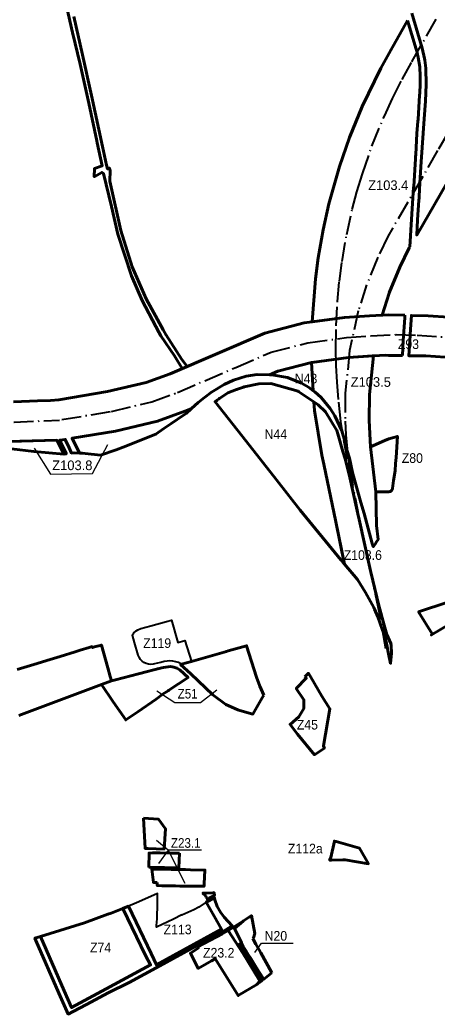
# Model space of a CAD drawing. Extents: x -650277 to -643422, y -1073980 to -1066720.
# Drawn here: x -648765 to -647728, y -1070690 to -1068218 of the extents above; entities that cross this region are included whole.
import ezdxf

# ---------------------------------------------------------------- set-up
doc = ezdxf.new("R2010")
doc.units = 0
doc.header["$LTSCALE"] = 9.6
doc.header["$PDMODE"] = 32
doc.header["$PDSIZE"] = 4.8
doc.linetypes.add('DOT_DASHED', pattern=[7.7, 5, -1.2, 0.3, -1.2])
for name, color, linetype, lineweight in [('1', 7, 'Continuous', 60), ('15', 7, 'Continuous', 60), ('2', 7, 'Continuous', 40), ('3', 7, 'Continuous', 60), ('35', 7, 'Continuous', 60), ('36', 7, 'Continuous', 60), ('40', 7, 'Continuous', 60), ('42', 7, 'Continuous', 60), ('59', 7, 'Continuous', 25), ('60', 7, 'Continuous', 60), ('61', 7, 'Continuous', 60), ('62', 7, 'DOT_DASHED', 40), ('63', 7, 'Continuous', 25), ('7', 7, 'Continuous', 60), ('9', 7, 'Continuous', 60)]:
    doc.layers.add(name, color=color, linetype=linetype, lineweight=lineweight)

msp = doc.modelspace()

# ---------------------------------------------------------------- linework, layer by layer
at = {"layer": '1', "lineweight": 40}
msp.add_lwpolyline([(-648339.05, -1069812.45), (-648363.68, -1069819.31), (-648371.21, -1069815.56), (-648378.1, -1069813.29), (-648385.21, -1069811.91), (-648392.45, -1069811.44), (-648399.68, -1069811.88), (-648406.84, -1069813.23), (-648414.657, -1069815.246), (-648415.99, -1069815.59), (-648430.881, -1069818.663), (-648433.97, -1069819.3), (-648439.89, -1069819.97), (-648445.8, -1069819.51), (-648451.53, -1069817.98), (-648456.88, -1069815.39), (-648461.64, -1069811.86), (-648465.67, -1069807.49), (-648468.82, -1069802.44), (-648470.97, -1069796.9), (-648480.267, -1069765.316), (-648485.44, -1069747.39), (-648485.14, -1069746.55), (-648483.274, -1069743.777), (-648481.79, -1069741.57), (-648477.39, -1069737.44), (-648476.022, -1069736.525), (-648472.4, -1069734.1), (-648464.45, -1069730.89), (-648439.8, -1069724.19), (-648401.288, -1069713.154), (-648388.631, -1069709.738), (-648372.639, -1069765.241), (-648355.015, -1069760.287)], close=True, dxfattribs=at)
at = {"layer": '1'}
msp.add_lwpolyline([(-648458.28, -1070202.26), (-648454.038, -1070277.767), (-648446.18, -1070278.15), (-648406.8, -1070279.32), (-648403.04, -1070229.15), (-648420.7, -1070204.96)], close=True, dxfattribs=at)
for points in [[(-648368.25, -1070289.71), (-648372.1, -1070289.59), (-648380.97, -1070289.44), (-648392.94, -1070289.25), (-648416.93, -1070288.85), (-648420.39, -1070288.79), (-648428.98, -1070288.92), (-648435.93, -1070288.95), (-648444.15, -1070289.16), (-648444.85, -1070324.47)], [(-648444.85, -1070324.47), (-648444.85, -1070324.47), (-648430.02, -1070324.76), (-648418.1, -1070325), (-648406.09, -1070325.23), (-648394.08, -1070325.47), (-648382.06, -1070325.7), (-648370.07, -1070325.94), (-648368.25, -1070289.71)], [(-648307.13, -1070365.57), (-648305.47, -1070331.23), (-648341.46, -1070330.48), (-648353.32, -1070330.23), (-648365.35, -1070329.98), (-648389.43, -1070329.58), (-648401.41, -1070329.39), (-648413.45, -1070329.19), (-648425.43, -1070329), (-648437.65, -1070328.8), (-648433.46, -1070361.94), (-648424.31, -1070362.21)], [(-648424.31, -1070362.21), (-648424.05, -1070370), (-648412.75, -1070370.28), (-648401.35, -1070370.5), (-648390.06, -1070370.72), (-648378.73, -1070370.94), (-648367.67, -1070371.16), (-648355.67, -1070371.28), (-648343.67, -1070371.41), (-648331.67, -1070371.53), (-648319.67, -1070371.65), (-648307.67, -1070371.78), (-648307.13, -1070365.57)]]:
    msp.add_lwpolyline(points, dxfattribs=at)
at = {"layer": '15'}
for points in [[(-648349.419, -1069079.223), (-648362.06, -1069084.664), (-648381.44, -1069052.48), (-648415.29, -1069003.16), (-648419.78, -1068994.25), (-648427.21, -1068980.13), (-648461.22, -1068915.44), (-648488.09, -1068854.16), (-648521.92, -1068750.34), (-648537.29, -1068681.95), (-648557.4, -1068599.9), (-648559.44, -1068598.37), (-648561.49, -1068596.84), (-648580.66, -1068607.64), (-648579.97, -1068587.39), (-648560.79, -1068580.12), (-648572.95, -1068522.97), (-648573.96, -1068518.34), (-648594.38, -1068425.02), (-648615.87, -1068327.3), (-648634.84, -1068248.76), (-648655.88, -1068153.63)], [(-648630.99, -1068209.19), (-648610.14, -1068304.32), (-648587.39, -1068405.82), (-648559.91, -1068532.62), (-648549.84, -1068578.65), (-648547.25, -1068588.14), (-648542.93, -1068586.13), (-648541.74, -1068589.27)], [(-648541.74, -1068589.27), (-648541.25, -1068592.3), (-648541.89, -1068618.64), (-648514.35, -1068741.53), (-648486.25, -1068831.83), (-648451.76, -1068910.91), (-648409.15, -1068988.44), (-648402.76, -1069000.2), (-648363.11, -1069061.72), (-648349.419, -1069079.223)], [(-648213.87, -1070524.8), (-648221.359, -1070516.349), (-648215.48, -1070512.59), (-648214.34, -1070511.86), (-648231.53, -1070476.99), (-648210.48, -1070458.42), (-648247.67, -1070481.57), (-648211, -1070538)], [(-648176.54, -1070616.09), (-648169.28, -1070610.49), (-648163.8, -1070606.27), (-648213.87, -1070524.8)], [(-648211, -1070538), (-648168.575, -1070607.847), (-648176.54, -1070616.09)]]:
    msp.add_lwpolyline(points, dxfattribs=at)
for points in [[(-648550.72, -1070626.869), (-648636.757, -1070673.431), (-648655.178, -1070631.294), (-648714.161, -1070496.376), (-648728.255, -1070500.709), (-648725.835, -1070506.221), (-648668.207, -1070637.453), (-648645.331, -1070689.546), (-648632.652, -1070682.82), (-648599.66, -1070665.32), (-648545.76, -1070636.22), (-648494.04, -1070610.73), (-648417.855, -1070569.57), (-648325.21, -1070518.84), (-648264.56, -1070486.34), (-648260.57, -1070484.2), (-648237.475, -1070470.361), (-648257.96, -1070448.17), (-648266.416, -1070436.404), (-648274.808, -1070421.647), (-648280.974, -1070405.11), (-648281.388, -1070400.523), (-648302.01, -1070411.05), (-648282.01, -1070446.35), (-648263.859, -1070478.393), (-648425.835, -1070567.021), (-648439.409, -1070538.729), (-648495.666, -1070421.476), (-648509.227, -1070426.957), (-648452.97, -1070544.21), (-648440.531, -1070567.236)], [(-648303.705, -1070395.035), (-648302.028, -1070398.436), (-648299.32, -1070403.93), (-648295.18, -1070401.23), (-648281.907, -1070394.762), (-648282.582, -1070387.276), (-648284.37, -1070387.85), (-648310.275, -1070388.476)]]:
    msp.add_lwpolyline(points, close=True, dxfattribs=at)
msp.add_point((-648213.87, -1070524.8), dxfattribs=at)
at = {"layer": '2'}
msp.add_lwpolyline([(-648495.666, -1070421.476), (-648439.409, -1070538.729), (-648425.835, -1070567.021), (-648267.801, -1070480.55), (-648263.859, -1070478.393), (-648282.01, -1070446.35), (-648302.01, -1070411.05), (-648320.24, -1070423.64), (-648332.97, -1070430.18), (-648362.79, -1070443.63), (-648363.1, -1070443.1), (-648383.61, -1070453.86), (-648426.05, -1070473.34), (-648425.71, -1070468.87), (-648424.47, -1070452.7), (-648423.56, -1070413.35), (-648423.005, -1070389.357), (-648469.77, -1070410.47), (-648481.18, -1070415.62)], close=True, dxfattribs=at)
at = {"layer": '3'}
msp.add_lwpolyline([(-648767.83, -1069946.87), (-648562.242, -1069870.301), (-648537.86, -1069861.22), (-648541.06, -1069849.78), (-648546.97, -1069828.68), (-648562.87, -1069771.85), (-648579.63, -1069776.66), (-648584.65, -1069778.1), (-648586.09, -1069775.75), (-648593.59, -1069778.06), (-648615.88, -1069784.93), (-648627.99, -1069788.67), (-648665.05, -1069799.99), (-648698.31, -1069810.16), (-648722.24, -1069817.54), (-648772.48, -1069832.83)], dxfattribs=at)
for points in [[(-648159.1, -1069896.39), (-648169.15, -1069873.81), (-648176.78, -1069851.74), (-648201.83, -1069773.86), (-648247.27, -1069786.64), (-648251.94, -1069787.95), (-648339.05, -1069812.45), (-648363.68, -1069819.31), (-648365.81, -1069819.9), (-648340.38, -1069843.78), (-648285.62, -1069895.71), (-648253.13, -1069919.7), (-648223.99, -1069932.96), (-648218.245, -1069934.595), (-648186.268, -1069943.697), (-648160.04, -1069897.73)], [(-648470.79, -1069843.51), (-648528.11, -1069858.73), (-648537.86, -1069861.22), (-648562.242, -1069870.301), (-648533.79, -1069913.49), (-648502.048, -1069957.969), (-648472.6, -1069937.81), (-648426.82, -1069906.88), (-648409.44, -1069893.25), (-648396.87, -1069885.43), (-648395.03, -1069884.22), (-648347.06, -1069853), (-648367.64, -1069833.35), (-648374.89, -1069829.22), (-648382.8, -1069826.55), (-648391.08, -1069825.45), (-648408.45, -1069827.83), (-648412.74, -1069828.72), (-648422.75, -1069830.78), (-648435.53, -1069834.44), (-648447.98, -1069837.44)], [(-648057.11, -1069851.12), (-648053.61, -1069854.64), (-648078.54, -1069880.01), (-648059.32, -1069908.27), (-648059.5, -1069929.52), (-648071.58, -1069950.39), (-648093.67, -1069969.42), (-648074.96, -1069993.46), (-648032.85, -1070044.73), (-648008.18, -1070028.25), (-648010.44, -1070023.66), (-648010.94, -1070022.65), (-647994.71, -1069930.53), (-648015.11, -1069898.98), (-648032.94, -1069867.46), (-648048.08, -1069841.95)]]:
    msp.add_lwpolyline(points, close=True, dxfattribs=at)
at = {"layer": '35'}
msp.add_lwpolyline([(-647740.74, -1069744.24), (-647742.36, -1069746.93), (-647674.901, -1069706.701), (-647560.36, -1069638.39), (-647570.37, -1069621.18), (-647701.61, -1069665.279), (-647774.11, -1069689.64)], close=True, dxfattribs=at)
at = {"layer": '36'}
for points in [[(-647962.82, -1070305.9), (-647956.36, -1070305.77), (-647898.82, -1070315.51), (-647921.51, -1070276.76), (-647979.24, -1070260.71), (-647983.6, -1070259.5), (-647992.71, -1070300.01), (-647995.46, -1070306.55), (-647991.12, -1070306.46)], [(-648636.757, -1070673.431), (-648550.72, -1070626.869), (-648440.531, -1070567.236), (-648452.97, -1070544.21), (-648509.227, -1070426.957), (-648526.28, -1070433.85), (-648538.611, -1070438.388), (-648546.377, -1070441.246), (-648604.92, -1070462.79), (-648714.161, -1070496.376), (-648655.178, -1070631.294)], [(-648636.757, -1070673.431), (-648550.72, -1070626.869), (-648440.531, -1070567.236), (-648452.97, -1070544.21), (-648509.227, -1070426.957), (-648526.28, -1070433.85), (-648538.611, -1070438.388), (-648546.377, -1070441.246), (-648604.92, -1070462.79), (-648714.161, -1070496.376), (-648655.178, -1070631.294)]]:
    msp.add_lwpolyline(points, close=True, dxfattribs=at)
at = {"layer": '40'}
msp.add_line((-648214.34, -1070511.86), (-648215.48, -1070512.59), dxfattribs=at)
for points in [[(-648186.441, -1070501.65), (-648186.088, -1070501.313), (-648184.791, -1070500.073), (-648181.386, -1070488.724), (-648189.93, -1070444.71), (-648194.56, -1070447.8), (-648194.56, -1070447.799), (-648209.82, -1070457.98), (-648210.48, -1070458.42), (-648231.53, -1070476.99), (-648214.34, -1070511.86)], [(-648215.48, -1070512.59), (-648210.19, -1070521.07), (-648203.83, -1070531.25), (-648197.59, -1070541.27), (-648190.71, -1070552.3), (-648182.98, -1070564.68), (-648171.02, -1070583.86), (-648159.23, -1070602.75), (-648138.93, -1070587.1)], [(-648166.63, -1070537.28), (-648170.72, -1070529.92), (-648172.96, -1070525.9), (-648178.7, -1070515.58), (-648184.54, -1070505.07), (-648186.441, -1070501.65)], [(-648138.93, -1070587.1), (-648140.05, -1070585.09), (-648166.63, -1070537.28)]]:
    msp.add_lwpolyline(points, dxfattribs=at)
at = {"layer": '42'}
msp.add_lwpolyline([(-648100.37, -1069107.1), (-648065.16, -1069121.12), (-648048.06, -1069130.81), (-648036.291, -1069139.458), (-648040.705, -1069069.547), (-648124.327, -1069091.181), (-648144.867, -1069099.987), (-648139.27, -1069100.05), (-648100.37, -1069107.1)], close=True, dxfattribs=at)
at = {"layer": '60'}
for points in [[(-647864.531, -1068951.823), (-647895.901, -1068953.392), (-647958.168, -1068957.73), (-648038.596, -1068968.281), (-648038.759, -1068968.54)], [(-647808.28, -1068952.066), (-647850.043, -1068951.098), (-647864.531, -1068951.823)], [(-647814.401, -1069052.246), (-647812.34, -1069014.54), (-647808.67, -1068958.06), (-647808.28, -1068952.066)], [(-647699.561, -1068956.635), (-647749.978, -1068953.416), (-647792.01, -1068952.442), (-647794.21, -1068986.12), (-647796.13, -1069015.57), (-647798.631, -1069052.508), (-647756.441, -1069053.207), (-647708.401, -1069056.275)], [(-648038.759, -1068968.54), (-648038.746, -1068968.301), (-648058.764, -1068970.927), (-648156.739, -1068996.273), (-648392.002, -1069097.554), (-648451.865, -1069119.456), (-648547.243, -1069141.81), (-648668.959, -1069161.838), (-648688.912, -1069163.603), (-648721.315, -1069164.952), (-648781.015, -1069167.44)], [(-648040.705, -1069069.547), (-648039.666, -1069069.279), (-647948.18, -1069057.276), (-647886.615, -1069053.052), (-647856.541, -1069051.548), (-647848.615, -1069051.679), (-647842.888, -1069051.774), (-647814.401, -1069052.246)], [(-648918.889, -1069268.875), (-648673.267, -1069262.895), (-648656.242, -1069297.116), (-648650.06, -1069296.39), (-648650.58, -1069295.34), (-648658.18, -1069280.27), (-648666.827, -1069262.738), (-648665.007, -1069262.694), (-648665.007, -1069262.694), (-648652.716, -1069260.657), (-648642.74, -1069281.93), (-648636.85, -1069294.49), (-648630.82, -1069293.63), (-648617.434, -1069294.508), (-648635.818, -1069257.857), (-648527.693, -1069239.938), (-648423.173, -1069215.44), (-648354.978, -1069190.492), (-648338.523, -1069183.389), (-648322.14, -1069168.56), (-648306.83, -1069156.57), (-648289.25, -1069142.79), (-648257.5, -1069124.41), (-648234.22, -1069113.6), (-648202.46, -1069103.3), (-648175.65, -1069099.64), (-648144.866, -1069099.987), (-648124.327, -1069091.181), (-648040.705, -1069069.547)], [(-648526.15, -1069286.21), (-648508.95, -1069280.01), (-648427.08, -1069247.75), (-648407.73, -1069233.88), (-648389.91, -1069221.86), (-648355.81, -1069198.88), (-648351.77, -1069195.88), (-648338.523, -1069183.389), (-648354.978, -1069190.492)], [(-648354.978, -1069190.492), (-648423.173, -1069215.44), (-648527.693, -1069239.938), (-648635.818, -1069257.857)], [(-648635.818, -1069257.857), (-648622.995, -1069283.455), (-648617.434, -1069294.508)], [(-648617.434, -1069294.508), (-648609.425, -1069295.033), (-648603.228, -1069295.53), (-648565.18, -1069299.46), (-648526.15, -1069286.21)]]:
    msp.add_lwpolyline(points, dxfattribs=at)
for points in [[(-648730.66, -1069290.43), (-648656.242, -1069297.116), (-648673.267, -1069262.895), (-648761.189, -1069265.035), (-648918.889, -1069268.875), (-648909.86, -1069270.02), (-648861.49, -1069275.34), (-648785.92, -1069284.2), (-648730.66, -1069290.43)], [(-647860.52, -1069390.72), (-647848.24, -1069390.65), (-647845.25, -1069390.07), (-647843.41, -1069389.23), (-647841.81, -1069387.99), (-647840.42, -1069386.51), (-647839.4, -1069384.73), (-647838.79, -1069382.86), (-647836.2, -1069362.68), (-647832.29, -1069338.58), (-647832.29, -1069338.58), (-647831.19, -1069320.69), (-647830.23, -1069305.38), (-647826.928, -1069253.199), (-647848.17, -1069259.21), (-647858.37, -1069263.03), (-647893.553, -1069279.017), (-647880.326, -1069390.832)]]:
    msp.add_lwpolyline(points, close=True, dxfattribs=at)
msp.add_arc((-648354.978, -1069190.492), 0.000000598, 264.13978, 298.69712, dxfattribs=at)
at = {"layer": '61'}
msp.add_line((-648038.596, -1068968.281), (-647958.168, -1068957.73), dxfattribs=at)
for points in [[(-647791.055, -1068200.507), (-647765.22, -1068287.94), (-647759.412, -1068313.436)], [(-647801.797, -1068219.34), (-647843.6, -1068292.629), (-647868.214, -1068337.803), (-647914.339, -1068432.512), (-647946.187, -1068510.254), (-647971.074, -1068581.98), (-647997.27, -1068674.747), (-648011.775, -1068739.718), (-648023.914, -1068809.332), (-648030.73, -1068861.213), (-648038.596, -1068968.281)], [(-647771.413, -1068334.626), (-647774.94, -1068311.47), (-647779.55, -1068292.23), (-647780.07, -1068290.53), (-647801.797, -1068219.34)], [(-647768.02, -1068570.36), (-647770.94, -1068622.47), (-647772.85, -1068656.41), (-647773.08, -1068660.57), (-647773.4, -1068665.71), (-647776.5, -1068714.8), (-647778.95, -1068752.433), (-647675.054, -1068572.919), (-647535.844, -1068336.279), (-647464.94, -1068215.752)], [(-647759.412, -1068313.436), (-647758.45, -1068317.66), (-647756.09, -1068337.61), (-647754.99, -1068378.21), (-647757.41, -1068419.98), (-647760.22, -1068463.96), (-647768.02, -1068570.36)], [(-647796.173, -1068782.191), (-647791.77, -1068713.23), (-647786.47, -1068634.37), (-647786.32, -1068632.19), (-647781.85, -1068562.97), (-647781.55, -1068558.38), (-647781.13, -1068551.88), (-647778.24, -1068499.95), (-647775.82, -1068469.74), (-647775.52, -1068464.97), (-647771.74, -1068404.5), (-647771.47, -1068400.07), (-647770.12, -1068377.5), (-647769.92, -1068352.1), (-647770.81, -1068340.29), (-647771.05, -1068337.01), (-647771.413, -1068334.626)], [(-647846.989, -1068896.545), (-647820.883, -1068832.117), (-647797.632, -1068784.713), (-647796.173, -1068782.191)], [(-647958.168, -1068957.73), (-647895.901, -1068953.392), (-647864.531, -1068951.823), (-647847.197, -1068897.199), (-647847.034, -1068896.687), (-647846.989, -1068896.545)], [(-647948.18, -1069057.276), (-648039.666, -1069069.279), (-648040.705, -1069069.548), (-648036.291, -1069139.458)], [(-647886.615, -1069053.052), (-647889.927, -1069053.218), (-647948.18, -1069057.276)], [(-647893.553, -1069279.017), (-647896.67, -1069213.573), (-647896.362, -1069149.171), (-647886.615, -1069053.052)], [(-648036.291, -1069139.458), (-648031.92, -1069142.67), (-648016.36, -1069156.54), (-647993.8, -1069184.11)], [(-648005.47, -1069192.09), (-648024.02, -1069174.7), (-648034.421, -1069167.61)], [(-648034.421, -1069167.61), (-648034.421, -1069167.61), (-648033, -1069189), (-648015, -1069300), (-648010.092, -1069322.087), (-647980.331, -1069465.915), (-647958.34, -1069570.699), (-647925.99, -1069608.57), (-647906.16, -1069641.48), (-647885.665, -1069678.788), (-647885.663, -1069678.794), (-647883.51, -1069682.71), (-647875.82, -1069701.85), (-647875.82, -1069701.85), (-647864.19, -1069735.12), (-647858.44, -1069749.43), (-647852.63, -1069775.7), (-647850.66, -1069785.74), (-647849.165, -1069793.367)], [(-647993.8, -1069184.11), (-647982.58, -1069202.33), (-647965.06, -1069238.95), (-647957.56, -1069264.74), (-647953.01, -1069285.73), (-647951.841, -1069289.09)], [(-647962.2, -1069290.88), (-647974.81, -1069246.86), (-647977.29, -1069238.21), (-648005.47, -1069192.09)], [(-647880.326, -1069390.832), (-647880.326, -1069390.832), (-647893.553, -1069279.017)], [(-647852.78, -1069745.71), (-647859.722, -1069722.428), (-647872.87, -1069673.56), (-647892.79, -1069591.06), (-647892.789, -1069591.06), (-647893.75, -1069587.08), (-647922.04, -1069459.71), (-647925.16, -1069445.68), (-647928.41, -1069431.03), (-647945.28, -1069355.1), (-647956.27, -1069311.58), (-647962.2, -1069290.88)], [(-647951.841, -1069289.09), (-647945.63, -1069306.95), (-647938.77, -1069343.17), (-647918.08, -1069417.43), (-647909.67, -1069444.46), (-647889.22, -1069519.32), (-647887.087, -1069527.229), (-647885.782, -1069525.389), (-647882.551, -1069520.835), (-647878.73, -1069515.45)], [(-647878.73, -1069515.45), (-647874.75, -1069509.84), (-647878.93, -1069475.09), (-647880.318, -1069391.297), (-647880.326, -1069390.832)], [(-647841.402, -1069792.351), (-647842.489, -1069773.282), (-647842.622, -1069770.956), (-647843.337, -1069769.013), (-647843.443, -1069768.293), (-647852.78, -1069745.71)], [(-647849.165, -1069793.367), (-647843.74, -1069817.63), (-647841.402, -1069792.351)]]:
    msp.add_lwpolyline(points, dxfattribs=at)
at = {"layer": '62'}
for points in [[(-647128.118, -1067439.088), (-647164.761, -1067539.408), (-647210.113, -1067645.071), (-647251.182, -1067728.502), (-647325.296, -1067860.04), (-647512.903, -1068178.95), (-647726.877, -1068542.68), (-647850.594, -1068756.441), (-647875.691, -1068807.609), (-647903.473, -1068876.174), (-647924.037, -1068940.973), (-647945.559, -1069039.601), (-647956.348, -1069145.994), (-647956.677, -1069214.977), (-647954.925, -1069248.93), (-647950.785, -1069292.731), (-647945.699, -1069329.377), (-647937.748, -1069374.683)], [(-647855.282, -1069780.988), (-647871.488, -1069692.474), (-647887.497, -1069616.134), (-647904.75, -1069533.925), (-647921.593, -1069453.674), (-647951.177, -1069310.704), (-647961.781, -1069251.651), (-647967.108, -1069216.048), (-647973.483, -1069161.422), (-647976.974, -1069118.566), (-647979.115, -1069076.622), (-647979.994, -1069035.633), (-647979.227, -1068978.642), (-647975.845, -1068917.741), (-647971.102, -1068867.969), (-647964.589, -1068818.397), (-647952.909, -1068751.415), (-647938.965, -1068688.958), (-647927.463, -1068645.455), (-647913.969, -1068600.436), (-647890.042, -1068531.477), (-647859.34, -1068456.533), (-647839.124, -1068413.001), (-647815.115, -1068365.753), (-647791.193, -1068321.849), (-647729.261, -1068213.27)], [(-647953.174, -1069007.503), (-647892.914, -1069003.305), (-647829.936, -1069000.155), (-647777.98, -1069001.73), (-647703.981, -1069006.455), (-647634.706, -1069014.33), (-647507.176, -1069026.93), (-647422.156, -1069034.805), (-647341.859, -1069041.105), (-647269.435, -1069044.255), (-647198.585, -1069044.255), (-647126.161, -1069041.105), (-647071.055, -1069037.955), (-646992.775, -1069025.505), (-646951.398, -1069008.03), (-646907.314, -1068982.831), (-646861.655, -1068949.756), (-646819.145, -1068907.232), (-646779.784, -1068863.132), (-646712.083, -1068781.233), (-646669.79, -1068726.705)], [(-648660.841, -1069211.175), (-648537.468, -1069190.874), (-648437.519, -1069167.448), (-648373.49, -1069144.023), (-648228.701, -1069081.527), (-648140.533, -1069043.727), (-648049.215, -1069020.103), (-647953.174, -1069007.503)], [(-649319.032, -1069251.01), (-649228.433, -1069229.954), (-649166.697, -1069221.478), (-649075.909, -1069222.689), (-648779.53, -1069217.422), (-648667.088, -1069212.737)]]:
    msp.add_lwpolyline(points, dxfattribs=at)
at = {"layer": '63'}
for q in [(-648421, -1070315), (-648355.27, -1070364.25)]:
    msp.add_line((-648397, -1070282), q, dxfattribs=at)
for points in [[(-648730, -1069282), (-648689.019, -1069347.095), (-648585, -1069345.095), (-648547, -1069273)], [(-648425, -1069886), (-648380, -1069915), (-648316, -1069915), (-648276, -1069883)], [(-648314, -1070282), (-648397, -1070282), (-648426, -1070258)], [(-648181, -1070536), (-648165, -1070513), (-648086, -1070513)]]:
    msp.add_lwpolyline(points, dxfattribs=at)
at = {"layer": '7'}
msp.add_lwpolyline([(-648247.67, -1070481.57), (-648262.69, -1070489.67), (-648323.59, -1070522.48), (-648322.18, -1070525.44), (-648341.41, -1070538.42), (-648322.16, -1070575.76), (-648289.22, -1070557.15), (-648279.736, -1070551.783), (-648278.89, -1070553.14), (-648222.58, -1070643.48), (-648176.54, -1070616.09), (-648168.575, -1070607.847), (-648211, -1070538)], close=True, dxfattribs=at)
at = {"layer": '9'}
msp.add_lwpolyline([(-648015, -1069300), (-648033, -1069189), (-648034.421, -1069167.61), (-648071.9, -1069142.06), (-648073.66, -1069140.86), (-648141.92, -1069121.66), (-648171.14, -1069122.83), (-648207.77, -1069129.95), (-648209.89, -1069130.36), (-648226.51, -1069136.57), (-648248.14, -1069144.65), (-648268.87, -1069158.61), (-648270.92, -1069159.99), (-648275.19, -1069162.87), (-648280.1, -1069166.97), (-648203.01, -1069264.73), (-648127.77, -1069361.38), (-648068.71, -1069436.57), (-647967.53, -1069559.94), (-647958.214, -1069571.3), (-647980.331, -1069465.915), (-648010.092, -1069322.087)], close=True, dxfattribs=at)

# ---------------------------------------------------------------- texts
at = {"layer": '59', "width": 0.95}
msp.add_text('Z113', height=24, dxfattribs=at).set_placement((-648408, -1070491))
at = {"layer": '63'}
for s, p in [('Z103.4', (-647899.646, -1068640.598)), ('Z103.5', (-647942.96, -1069129.881)), ('Z103.8', (-648685, -1069337))]:
    msp.add_text(s, height=24, dxfattribs=at).set_placement(p)
for s, width, p in [('Z93', 0.95, (-647825.651, -1069035.867)), ('N43', 0.95, (-648081.963, -1069121.387)), ('N44', 0.95, (-648157.12, -1069259.712)), ('Z80', 0.95, (-647816, -1069319)), ('Z103.6', 0.95, (-647960.304, -1069560.198)), ('Z119', 0.95, (-648458.914, -1069779.092)), ('Z51', 0.9, (-648373.214, -1069904.865)), ('Z45', 0.95, (-648077, -1069982)), ('Z23.1', 0.9, (-648390, -1070276)), ('Z112a', 0.95, (-648099, -1070290)), ('N20', 0.95, (-648157, -1070507)), ('Z74', 0.95, (-648591, -1070536)), ('Z23.2', 0.95, (-648310, -1070549))]:
    msp.add_text(s, height=24, dxfattribs=dict(at, width=width)).set_placement(p)

doc.saveas('drawing.dxf')
